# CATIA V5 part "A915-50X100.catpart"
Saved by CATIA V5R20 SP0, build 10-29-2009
Part number: A915-50X100
Source: Unknown
Property "A": "0.000"
Property "ARTICLENO": "A915-50X100"
Property "BOMINFO": "A915-50X100"
Property "CODE": "A915-50X100"
Property "CREATOR": "CADENAS GmbH"
Property "D": "13.500"
Property "D1": "20.000"
Property "FORM": "B"
Property "L": "100.000"
Property "L1": "25.000"
Property "L2": "50.000"
Property "LINA": "A915-50X100"
Property "NB": "A915-50X100"
Property "NBSYN": "$CODE."
Property "NN": "A915"
Property "NT": "VDI 3357 Wear Plates, steel"
Property "SCREW": "M12x25"
Property "SUPPLIER": "CF"
Property "T": "13.000"
Property "W": "50.000"
Bounding box of the stored display mesh (mm): x 0 to 20, y 0 to 100, z -25 to 25
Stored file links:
  C:\Users\borellobunino\Desktop\3D X SITO CF\A915\GSB_OILLESS_G22501050100\A915-50X100.catpart
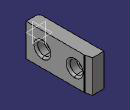
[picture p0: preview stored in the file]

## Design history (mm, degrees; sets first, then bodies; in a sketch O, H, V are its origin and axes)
Body1 "Geometry.1" (main body)
  Solid1 "A915-50X100.catpart": solid without history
